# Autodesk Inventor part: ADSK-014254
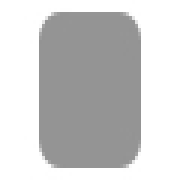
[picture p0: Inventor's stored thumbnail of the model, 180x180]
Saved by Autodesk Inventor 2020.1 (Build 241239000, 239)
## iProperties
Created: 2019-01
Part Number: ADSK-014254
Material: Stahl, weich
Document SubType Name: Modeling
Designer: lutzd
Language: de-DE
Size Designation: 5 x 89,384472 x 39,384472
Categories: <MemberInstance><Categories><Category DisplayName="Sonstige Bauteile" InternalName="5aa15e00-363f-49f2-933f-16f664388e3f" Mnemonic="OTHER"><Category DisplayName
Mass: 137.332 g
Surface Area: 82.4257 cm^2
Volume: 17.4945 cm^3
Density: 7.85 g/cm^3
Appearance: Semi-Polished(8)
IsCustomPart: 1
Title: end cap
Author: lutzd
Revision Number: -
Dimensions: 39,4x89,4x5 mm
Mass: 0,137 kg
DocNumber: ADSK-014254
Folder: 01 - Themengebiete\Simplification\01 - Packaging machine\ADSK-014200\Frame\
VDS_Category: 3D Komponenten
VDS_NumSchm: Autodesk
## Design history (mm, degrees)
sketch "Sketch1"
  geometry: L1 (0, 20.175)-(0, -21.446); L2 (-20.203, 0)-(20.169, 0); L3 (-19.692, 44.692)-(19.692, 44.692); L4 (19.692, 44.692)-(19.692, -44.692); L5 (19.692, -44.692)-(-19.692, -44.692); L6 (-19.692, -44.692)-(-19.692, 44.692); 1 further point
  constraints: 12 end point, 2 horizontal, 2 parallel, 2 point on line, 1 perpendicular, 1 vertical
  dimensions: "d0" = 89.38447 distance between parallel lines of L5 L3 (= height); "d1" = 44.69224 distance between parallel lines of L2 L3 (= 0.5 x height); "d2" = 39.38447 distance between parallel lines of L6 L4 (= width); "d3" = 19.69224 distance between parallel lines of L6 L1 (= 0.5 x width)
extrude "Extrusion1" new body sketch "Sketch1" distance "d4" = 5 (= thickness); taper "d5" = 0 deg
fillet "Fillet1" dims "d6" = 5 (= fillet), "d7" = 0, "fillet" = 5 [user parameter; used in 1 equation term]
chamfer "Chamfer1" distance "d8" = 0 (computed from chamfer); stored, may be unused: second distance "d9" = 2, angle "d10" = 45 deg; dims "d11" = 0, "chamfer" = 0 [user parameter; used in 1 equation term]
body "Solid1"
other parameters: "thickness" = 5 [user parameter; used in 1 equation term], "width" = 39.38447 [user parameter; used in 2 equation terms], "height" = 89.38447 [user parameter; used in 2 equation terms]
